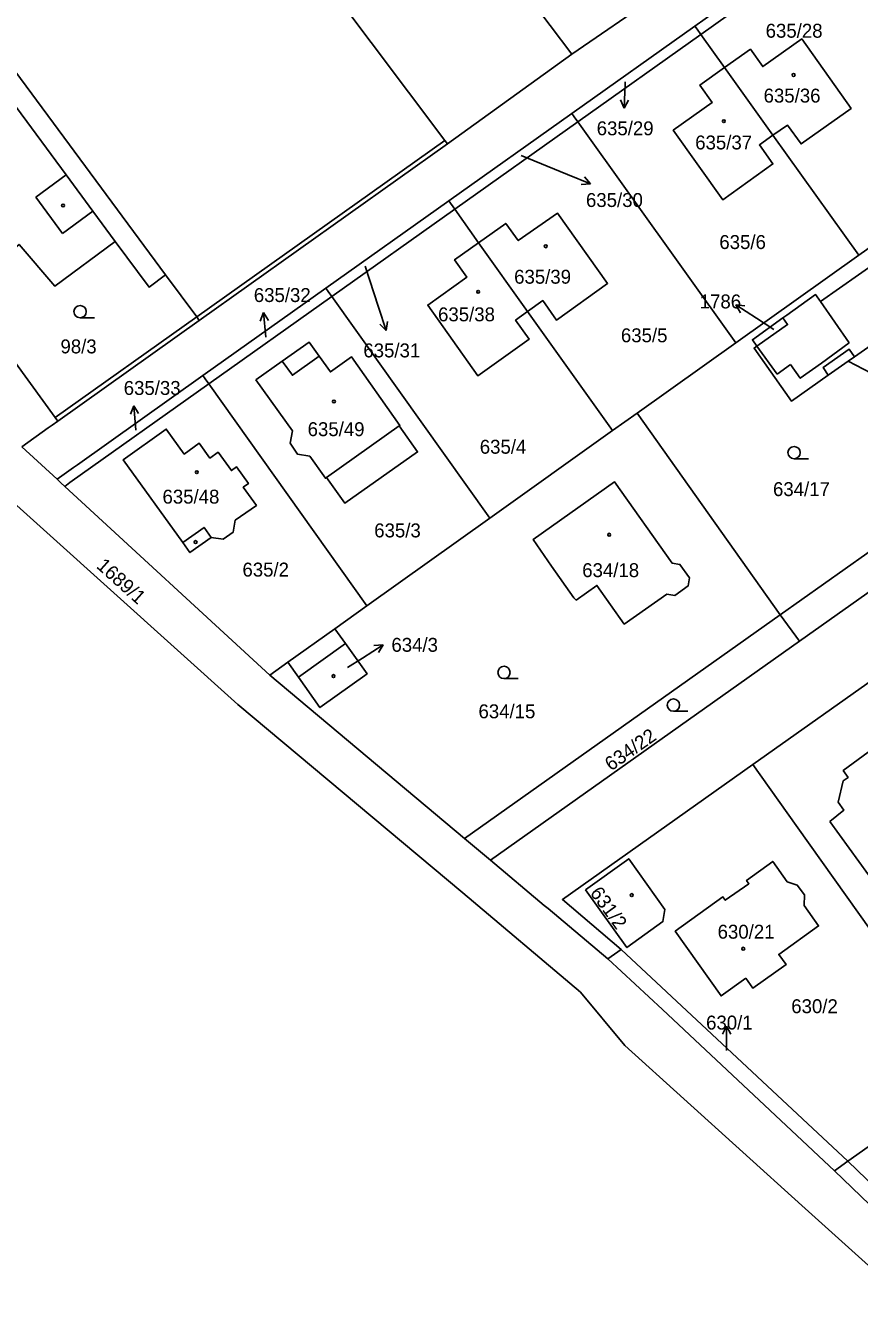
# Model space of a CAD drawing. Extents: x -724107 to -720612, y -1045267 to -1038441.
# Drawn here: x -723405.8 to -723303.9, y -1042898.3 to -1042742.2 of the extents above; entities that cross this region are included whole.
import ezdxf

# ---------------------------------------------------------------- set-up
doc = ezdxf.new("R2010")
doc.units = 0
for name, color, linetype in [('Hranice kat_území', 7, 'Continuous'), ('Hranice parcel', 7, 'Continuous'), ('Parcelní čísla', 7, 'Continuous'), ('Pop  PČ popisy', 7, 'Continuous'), ('Vnitřní kresba', 7, 'Continuous'), ('Značky budov', 7, 'Continuous'), ('Značky kultur', 7, 'Continuous')]:
    doc.layers.add(name, color=color, linetype=linetype)

msp = doc.modelspace()

# ---------------------------------------------------------------- linework, layer by layer
at = {"layer": 'Hranice kat_území'}
for points in [[(-723434.02, -1042774.34), (-723410.63, -1042797.61), (-723379.85, -1042825.28), (-723352.37, -1042848.3)], [(-723352.37, -1042848.3), (-723337.98, -1042860.44), (-723332.57, -1042866.98)], [(-723332.57, -1042866.98), (-723310.92, -1042886.54), (-723291.01, -1042904.47)]]:
    msp.add_lwpolyline(points, dxfattribs=at)
at = {"layer": 'Hranice parcel'}
for p, q in [((-723361.92, -1042715.35), (-723339.02, -1042745.73)), ((-723323.99, -1042742.3), (-723308.96, -1042731.61)), ((-723323.61, -1042735.14), (-723339.02, -1042745.73)), ((-723339.03, -1042752.99), (-723323.99, -1042742.3)), ((-723323.27, -1042743.32), (-723338.31, -1042754.01)), ((-723320.37, -1042747.38), (-723323.27, -1042743.32)), ((-723339.02, -1042745.73), (-723354.23, -1042756.72)), ((-723320.37, -1042747.38), (-723314.45, -1042755.66)), ((-723354.07, -1042763.68), (-723339.03, -1042752.99)), ((-723338.31, -1042754.01), (-723353.35, -1042764.7)), ((-723318.97, -1042781.03), (-723338.31, -1042754.01)), ((-723384.57, -1042778.3), (-723354.23, -1042756.72)), ((-723303.97, -1042770.33), (-723314.45, -1042755.66)), ((-723369.1, -1042774.37), (-723354.07, -1042763.68)), ((-723353.35, -1042764.7), (-723368.38, -1042775.39)), ((-723354.07, -1042763.68), (-723353.35, -1042764.7)), ((-723350.42, -1042768.8), (-723353.35, -1042764.7)), ((-723298, -1042766.07), (-723303.97, -1042770.33)), ((-723344.43, -1042777.21), (-723350.42, -1042768.8)), ((-723303.97, -1042770.33), (-723318.97, -1042781.03)), ((-723384.13, -1042785.05), (-723369.1, -1042774.37)), ((-723368.38, -1042775.39), (-723383.41, -1042786.07)), ((-723349.06, -1042802.49), (-723368.38, -1042775.39)), ((-723334.04, -1042791.78), (-723344.43, -1042777.21)), ((-723401.85, -1042790.6), (-723384.57, -1042778.3)), ((-723318.97, -1042781.03), (-723331.04, -1042789.64)), ((-723364.07, -1042813.19), (-723383.41, -1042786.07)), ((-723331.04, -1042789.64), (-723334.04, -1042791.78)), ((-723313.55, -1042814.3), (-723331.04, -1042789.64)), ((-723280.38, -1042790.77), (-723313.55, -1042814.3)), ((-723334.04, -1042791.78), (-723349.06, -1042802.49)), ((-723401.95, -1042797.72), (-723406.27, -1042793.74)), ((-723311.19, -1042817.51), (-723278.06, -1042794.03)), ((-723375.95, -1042821.66), (-723401.01, -1042798.59)), ((-723349.06, -1042802.49), (-723364.07, -1042813.19)), ((-723364.07, -1042813.19), (-723368.01, -1042816)), ((-723352.14, -1042841.66), (-723313.55, -1042814.3)), ((-723313.55, -1042814.3), (-723311.19, -1042817.51)), ((-723368.01, -1042816), (-723373.76, -1042820.1)), ((-723311.19, -1042817.51), (-723348.99, -1042844.31)), ((-723373.76, -1042820.1), (-723375.95, -1042821.66)), ((-723300.34, -1042820.86), (-723316.92, -1042832.61)), ((-723375.95, -1042821.66), (-723352.14, -1042841.66)), ((-723348.99, -1042844.31), (-723352.14, -1042841.66)), ((-723333, -1042855.21), (-723334.63, -1042856.37)), ((-723305.28, -1042881.12), (-723333, -1042855.21)), ((-723290.09, -1042870.31), (-723305.28, -1042881.12)), ((-723305.28, -1042881.12), (-723306.91, -1042882.28))]:
    msp.add_line(p, q, dxfattribs=at)
for points in [[(-723428.99, -1042718.18), (-723428.67, -1042718.59), (-723388.68, -1042772.74)], [(-723354.23, -1042756.72), (-723354.54, -1042756.29), (-723377.02, -1042726.38)], [(-723308.24, -1042732.63), (-723312.53, -1042735.68), (-723323.27, -1042743.32)], [(-723323.99, -1042742.3), (-723323.72, -1042742.68), (-723323.27, -1042743.32)], [(-723320.37, -1042747.38), (-723317.21, -1042745.14), (-723315.7, -1042747.26), (-723310.92, -1042743.88), (-723304.9, -1042752.38), (-723311.01, -1042756.72), (-723312.69, -1042754.41), (-723314.45, -1042755.66)], [(-723314.45, -1042755.66), (-723316.1, -1042756.83), (-723314.46, -1042759.17), (-723320.59, -1042763.55), (-723326.64, -1042755.05), (-723321.86, -1042751.64), (-723323.37, -1042749.52), (-723320.37, -1042747.38)], [(-723394.83, -1042768.63), (-723397.57, -1042764.93), (-723400.84, -1042760.5), (-723406.92, -1042752.27)], [(-723339.03, -1042752.99), (-723338.75, -1042753.39), (-723338.31, -1042754.01)], [(-723350.42, -1042768.8), (-723347.11, -1042766.44), (-723345.57, -1042768.54), (-723340.77, -1042765.19), (-723334.65, -1042773.78), (-723340.92, -1042778.25), (-723342.59, -1042775.87), (-723344.43, -1042777.21)], [(-723401.85, -1042790.6), (-723402.17, -1042790.17), (-723413.44, -1042774.73), (-723406.58, -1042769.01), (-723402.22, -1042774.1), (-723394.83, -1042768.63)], [(-723388.68, -1042772.74), (-723390.69, -1042774.23), (-723394.83, -1042768.63)], [(-723344.43, -1042777.21), (-723345.9, -1042778.27), (-723344.24, -1042780.58), (-723350.52, -1042785.07), (-723356.64, -1042776.43), (-723351.87, -1042773.03), (-723353.36, -1042770.89), (-723350.42, -1042768.8)], [(-723313.24, -1042777.99), (-723312.75, -1042777.66), (-723309.24, -1042775.15), (-723308.64, -1042775.99), (-723299.33, -1042769.45), (-723290.65, -1042781.81), (-723295.49, -1042785.22), (-723296.95, -1042783.13), (-723300.59, -1042785.73), (-723305.24, -1042783.28), (-723307.69, -1042785), (-723312.2, -1042788.16), (-723316.75, -1042781.68), (-723316.41, -1042781.44)], [(-723388.68, -1042772.74), (-723384.88, -1042777.87), (-723384.57, -1042778.3)], [(-723369.1, -1042774.37), (-723368.82, -1042774.76), (-723368.38, -1042775.39)], [(-723316.41, -1042781.44), (-723316.96, -1042780.67), (-723313.24, -1042777.99)], [(-723313.24, -1042777.99), (-723312.66, -1042778.81), (-723316.41, -1042781.44)], [(-723377.66, -1042785.56), (-723374.43, -1042783.27), (-723371.14, -1042780.95), (-723369.92, -1042782.67), (-723368.54, -1042784.59), (-723365.97, -1042782.75), (-723360.05, -1042791.13), (-723360.15, -1042791.2), (-723357.89, -1042794.39), (-723366.77, -1042800.66), (-723369.03, -1042797.51), (-723369.14, -1042797.59), (-723371.06, -1042794.89), (-723372.56, -1042794.64), (-723373.46, -1042793.33), (-723373.19, -1042791.82), (-723377.66, -1042785.56)], [(-723401.95, -1042797.72), (-723399.93, -1042796.29), (-723399.44, -1042795.94), (-723384.13, -1042785.05)], [(-723384.13, -1042785.05), (-723383.86, -1042785.43), (-723383.41, -1042786.07)], [(-723383.41, -1042786.07), (-723400.37, -1042798.13), (-723401.01, -1042798.59)], [(-723406.27, -1042793.74), (-723403.04, -1042791.45), (-723402.55, -1042791.1), (-723401.85, -1042790.6)], [(-723386.59, -1042805.45), (-723393.87, -1042795.36), (-723388.61, -1042791.59), (-723386.41, -1042794.64), (-723384.56, -1042793.33), (-723383.26, -1042795.14), (-723382.27, -1042794.42), (-723380.64, -1042796.67), (-723380.01, -1042796.21), (-723378.56, -1042798.25), (-723379.19, -1042798.7), (-723377.59, -1042800.93), (-723380.18, -1042802.73), (-723380.43, -1042804.21), (-723381.65, -1042805.05), (-723383.11, -1042804.83), (-723385.71, -1042806.69), (-723386.59, -1042805.45)], [(-723401.01, -1042798.59), (-723401.49, -1042798.15), (-723401.95, -1042797.72)], [(-723327.41, -1042811.78), (-723332.63, -1042815.44), (-723335.97, -1042810.7), (-723338.52, -1042812.5), (-723338.77, -1042812.22), (-723341.5, -1042808.36), (-723343.77, -1042805.1), (-723333.8, -1042798.04), (-723326.77, -1042807.98), (-723325.81, -1042808.14), (-723324.65, -1042809.78), (-723324.82, -1042810.76), (-723326.45, -1042811.94), (-723327.41, -1042811.78)], [(-723373.76, -1042820.1), (-723372.45, -1042821.91), (-723369.82, -1042825.65), (-723364.06, -1042821.51), (-723366.71, -1042817.81), (-723368.01, -1042816)], [(-723307.48, -1042839.56), (-723305.78, -1042838.17), (-723306.49, -1042837.19), (-723305.87, -1042834.61), (-723305.26, -1042834.19), (-723305.86, -1042833.35), (-723299.29, -1042828.52), (-723292.14, -1042838.36), (-723302.79, -1042846.1), (-723307.48, -1042839.56)], [(-723316.92, -1042832.61), (-723340.18, -1042849.1), (-723333, -1042855.21)], [(-723290.09, -1042870.31), (-723311.62, -1042840.06), (-723316.92, -1042832.61)], [(-723334.63, -1042856.37), (-723341.94, -1042850.23), (-723342.42, -1042849.83), (-723348.99, -1042844.31)], [(-723337.37, -1042847.93), (-723332.07, -1042844.13), (-723327.65, -1042850.34), (-723327.89, -1042851.82), (-723332.29, -1042854.99), (-723337.37, -1042847.93)], [(-723317.77, -1042858.74), (-723320.79, -1042860.91), (-723326.38, -1042852.99), (-723320.56, -1042848.79), (-723320.27, -1042849.2), (-723317.39, -1042847.18), (-723317.68, -1042846.77), (-723314.47, -1042844.46), (-723312.71, -1042846.94), (-723311.47, -1042847.34), (-723310.6, -1042848.56), (-723310.63, -1042849.86), (-723308.87, -1042852.34), (-723313.73, -1042855.83), (-723312.85, -1042857.06), (-723316.89, -1042859.96), (-723317.77, -1042858.74)], [(-723306.91, -1042882.28), (-723327.96, -1042862.56), (-723334.63, -1042856.37)], [(-723264.4, -1042890.5), (-723282.38, -1042903.18), (-723305.28, -1042881.12)], [(-723279.63, -1042908.59), (-723287.64, -1042900.82), (-723306.91, -1042882.28)]]:
    msp.add_lwpolyline(points, dxfattribs=at)
at = {"layer": 'Pop  PČ popisy'}
for p, q in [((-723332.52, -1042749.36), (-723332.62, -1042752.36)), ((-723332.51, -1042749.11), (-723332.52, -1042749.36)), ((-723332.62, -1042752.36), (-723333.09, -1042751.34)), ((-723332.62, -1042752.36), (-723332.09, -1042751.38)), ((-723345.21, -1042758.14), (-723339.54, -1042760.46)), ((-723339.54, -1042760.46), (-723336.76, -1042761.58)), ((-723336.76, -1042761.58), (-723337.87, -1042761.67)), ((-723336.76, -1042761.58), (-723337.5, -1042760.74)), ((-723364.3, -1042771.68), (-723362.65, -1042776.7)), ((-723376.72, -1042777.34), (-723377.12, -1042778.39)), ((-723376.41, -1042780.33), (-723376.72, -1042777.34)), ((-723376.72, -1042777.34), (-723376.12, -1042778.29)), ((-723362.65, -1042776.7), (-723361.72, -1042779.55)), ((-723316.47, -1042778.04), (-723318.99, -1042776.41)), ((-723318.99, -1042776.41), (-723317.87, -1042776.53)), ((-723318.99, -1042776.41), (-723318.42, -1042777.37)), ((-723361.72, -1042779.55), (-723362.51, -1042778.76)), ((-723361.72, -1042779.55), (-723361.56, -1042778.45)), ((-723314.36, -1042779.43), (-723316.47, -1042778.04)), ((-723392.58, -1042788.73), (-723392.99, -1042789.77)), ((-723392.32, -1042791.72), (-723392.58, -1042788.73)), ((-723392.58, -1042788.73), (-723391.99, -1042789.68)), ((-723364.61, -1042819.58), (-723362.09, -1042817.95)), ((-723362.09, -1042817.95), (-723363.21, -1042818.07)), ((-723362.09, -1042817.95), (-723362.66, -1042818.91)), ((-723366.44, -1042820.75), (-723364.61, -1042819.58)), ((-723320.11, -1042864.59), (-723320.61, -1042865.59)), ((-723320.11, -1042867.59), (-723320.11, -1042864.59)), ((-723320.11, -1042864.59), (-723319.61, -1042865.59))]:
    msp.add_line(p, q, dxfattribs=at)
at = {"layer": 'Vnitřní kresba'}
for p, q in [((-723384.88, -1042777.87), (-723354.54, -1042756.29)), ((-723400.84, -1042760.5), (-723404.54, -1042763.23)), ((-723404.54, -1042763.23), (-723401.27, -1042767.66)), ((-723401.27, -1042767.66), (-723397.57, -1042764.93)), ((-723308.64, -1042775.99), (-723305.12, -1042781.06)), ((-723384.88, -1042777.87), (-723402.17, -1042790.17)), ((-723316.41, -1042781.44), (-723313.94, -1042784.88)), ((-723308.53, -1042783.53), (-723305.12, -1042781.06)), ((-723313.94, -1042784.88), (-723312.31, -1042783.71)), ((-723304.48, -1042782.75), (-723305.24, -1042783.28)), ((-723369.03, -1042797.51), (-723360.15, -1042791.2)), ((-723372.45, -1042821.91), (-723366.71, -1042817.81))]:
    msp.add_line(p, q, dxfattribs=at)
for points in [[(-723304.48, -1042782.75), (-723299.73, -1042779.42), (-723299.53, -1042779.43), (-723296.95, -1042783.13)], [(-723307.69, -1042785), (-723308.33, -1042784.07), (-723305.12, -1042781.83), (-723304.48, -1042782.75)], [(-723374.43, -1042783.27), (-723373.19, -1042785.01), (-723369.92, -1042782.67)], [(-723312.31, -1042783.71), (-723311.11, -1042785.38), (-723308.53, -1042783.53)], [(-723386.59, -1042805.45), (-723383.98, -1042803.61), (-723383.11, -1042804.83)]]:
    msp.add_lwpolyline(points, dxfattribs=at)
at = {"layer": 'Značky budov'}
for centre in [(-723311.92, -1042748.29), (-723320.45, -1042753.93), (-723401.21, -1042764.25), (-723342.22, -1042769.23), (-723350.48, -1042774.8), (-723368.11, -1042788.21), (-723384.87, -1042796.86), (-723385.01, -1042805.4), (-723334.46, -1042804.51), (-723368.16, -1042821.79), (-723331.71, -1042848.57), (-723318.08, -1042855.13)]:
    msp.add_circle(centre, 0.175, dxfattribs=at)
at = {"layer": 'Značky kultur'}
for p, q in [((-723399.14, -1042777.98), (-723397.39, -1042777.98)), ((-723311.87, -1042795.22), (-723310.12, -1042795.22)), ((-723347.32, -1042822.09), (-723345.57, -1042822.09)), ((-723326.62, -1042826.08), (-723324.87, -1042826.08))]:
    msp.add_line(p, q, dxfattribs=at)
for centre in [(-723399.14, -1042777.23), (-723311.87, -1042794.47), (-723347.32, -1042821.34), (-723326.62, -1042825.33)]:
    msp.add_circle(centre, 0.75, dxfattribs=at)

# ---------------------------------------------------------------- texts
at = {"layer": 'Parcelní čísla'}
for s, p in [('635/28', (-723315.34, -1042743.73)), ('635/36', (-723315.59, -1042751.66)), ('635/29', (-723335.99, -1042755.66)), ('635/37', (-723323.95, -1042757.39)), ('635/30', (-723337.3, -1042764.43)), ('635/6', (-723321, -1042769.57)), ('635/39', (-723346.08, -1042773.81)), ('635/32', (-723377.9, -1042776.05)), ('1786', (-723323.4, -1042776.83)), ('635/38', (-723355.38, -1042778.41)), ('98/3', (-723401.53, -1042782.33)), ('635/5', (-723333.03, -1042780.97)), ('635/31', (-723364.51, -1042782.82)), ('635/33', (-723393.8, -1042787.41)), ('635/49', (-723371.32, -1042792.45)), ('635/4', (-723350.28, -1042794.6)), ('635/48', (-723389.06, -1042800.7)), ('634/17', (-723314.44, -1042799.78)), ('635/3', (-723363.18, -1042804.83)), ('635/2', (-723379.29, -1042809.62)), ('634/18', (-723337.76, -1042809.69)), ('634/3', (-723361.08, -1042818.82)), ('634/15', (-723350.44, -1042826.95)), ('630/21', (-723321.21, -1042853.9)), ('630/2', (-723312.21, -1042863.01)), ('630/1', (-723322.62, -1042865.01))]:
    msp.add_text(s, height=1.7, dxfattribs=at).set_placement(p)
for s, rotation, p in [('1689/1', 318, (-723397.24, -1042808.47)), ('634/22', 35, (-723334.24, -1042833.46)), ('631/2', 306, (-723336.88, -1042848.32))]:
    msp.add_text(s, height=1.7, rotation=rotation, dxfattribs=at).set_placement(p)

doc.saveas('drawing.dxf')
